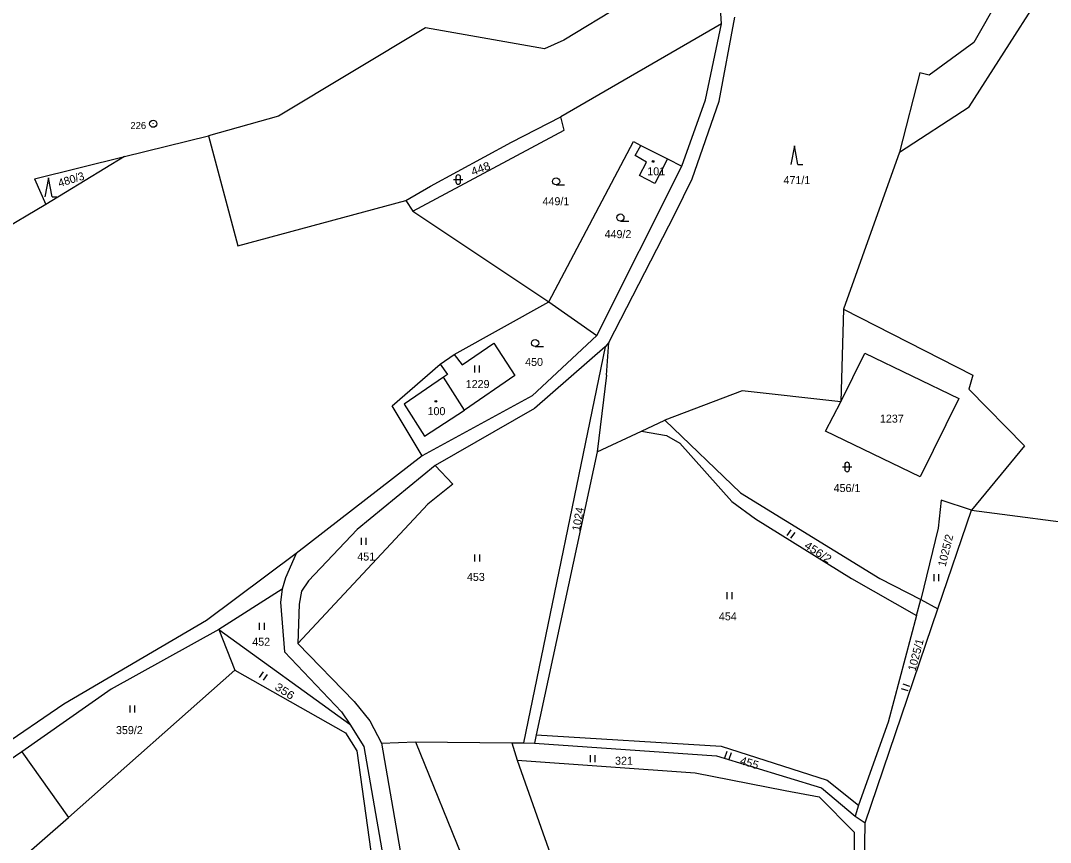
# Model space of a CAD drawing. Extents: x -744132 to -742433, y -984679 to -982287.
# Drawn here: x -743105 to -742886.3, y -983707.4 to -983532.9 of the extents above; entities that cross this region are included whole.
import ezdxf
from ezdxf.enums import TextEntityAlignment as Align

# ---------------------------------------------------------------- set-up
doc = ezdxf.new("R2010")
doc.units = 0
doc.header["$LTSCALE"] = 0.68
for name, color, linetype, lineweight in [('1', 7, 'Continuous', 25), ('3', 7, 'Continuous', 25), ('5', 7, 'Continuous', 25), ('8', 7, 'Continuous', 25)]:
    doc.layers.add(name, color=color, linetype=linetype, lineweight=lineweight)
doc.layers.add('2', color=7, linetype='Continuous')

msp = doc.modelspace()

# ---------------------------------------------------------------- linework, layer by layer
at = {"layer": '1'}
for p, q in [((-742956.14, -983533.56), (-742957.26, -983515.6)), ((-742894.51, -983523.48), (-742902.53, -983537.48)), ((-742903.5, -983551.14), (-742888.2, -983527.16)), ((-742977.21, -983529.47), (-742989.65, -983537)), ((-742956.63, -983549.96), (-742953.26, -983532.14)), ((-743018.99, -983534.41), (-743050.26, -983553.18)), ((-742993.73, -983538.86), (-743018.99, -983534.41)), ((-742956.14, -983533.56), (-742990.29, -983553.27)), ((-742959.5, -983549.65), (-742956.14, -983533.56)), ((-742989.65, -983537), (-742993.73, -983538.86)), ((-742902.53, -983537.48), (-742912, -983544.46)), ((-742914, -983543.94), (-742918.35, -983560.77)), ((-742912, -983544.46), (-742914, -983543.94)), ((-742964.56, -983563.78), (-742959.5, -983549.65)), ((-742962.39, -983566.49), (-742956.63, -983549.96)), ((-742918.35, -983560.77), (-742903.5, -983551.14)), ((-743050.26, -983553.18), (-743065.09, -983557.3)), ((-743000.72, -983558.65), (-742990.29, -983553.27)), ((-742989.58, -983556.09), (-742990.29, -983553.27)), ((-743082.91, -983561.73), (-743065.09, -983557.3)), ((-743065.09, -983557.3), (-743058.88, -983580.68)), ((-743021.72, -983573.33), (-742989.58, -983556.09)), ((-743017.91, -983568.01), (-743000.72, -983558.65)), ((-742992.82, -983592.6), (-742974.85, -983558.53)), ((-742974.85, -983558.53), (-742973.25, -983559.37)), ((-742974.44, -983561.53), (-742973.25, -983559.37)), ((-742973.25, -983559.37), (-742967.61, -983562.23)), ((-743102.08, -983566.47), (-743082.91, -983561.73)), ((-743082.91, -983561.73), (-743099.64, -983571.88)), ((-742972.06, -983562.91), (-742974.44, -983561.53)), ((-742918.35, -983560.77), (-742930.2, -983594.18)), ((-742982.6, -983599.76), (-742964.56, -983563.78)), ((-742973.54, -983565.78), (-742972.06, -983562.91)), ((-742967.61, -983562.23), (-742970.27, -983567.47)), ((-742967.61, -983562.23), (-742964.56, -983563.78)), ((-742970.27, -983567.47), (-742973.54, -983565.78)), ((-743102.08, -983566.47), (-743099.64, -983571.88)), ((-743023.21, -983571.09), (-743017.91, -983568.01)), ((-742966.04, -983573.96), (-742962.39, -983566.49)), ((-743099.64, -983571.88), (-743137.01, -983594.08)), ((-743058.88, -983580.68), (-743023.21, -983571.09)), ((-743023.21, -983571.09), (-743021.72, -983573.33)), ((-743021.72, -983573.33), (-742992.82, -983592.6)), ((-742980.03, -983601.25), (-742966.04, -983573.96)), ((-743012.88, -983603.78), (-742992.82, -983592.6)), ((-742992.82, -983592.6), (-742982.6, -983599.76)), ((-742930.2, -983594.18), (-742930.76, -983613.83)), ((-742930.2, -983594.18), (-742902.75, -983608.14)), ((-742982.6, -983599.76), (-742996.35, -983612.57)), ((-743011.23, -983605.95), (-743004.47, -983601.4)), ((-743004.47, -983601.4), (-743000.04, -983608.27)), ((-742980.83, -983602.15), (-742998.21, -983686.27)), ((-742980.83, -983602.15), (-742995.86, -983615.23)), ((-742980.03, -983601.25), (-742980.83, -983602.15)), ((-742980.53, -983608.16), (-742980.03, -983601.25)), ((-743015.87, -983605.82), (-743012.88, -983603.78)), ((-743012.88, -983603.78), (-743011.23, -983605.95)), ((-742925.68, -983603.47), (-742905.69, -983613.13)), ((-743026.07, -983614.71), (-743015.87, -983605.82)), ((-743015.87, -983605.82), (-743014.35, -983608.02)), ((-743015.18, -983608.62), (-743023.52, -983614.35)), ((-743014.35, -983608.02), (-743015.18, -983608.62)), ((-743000.04, -983608.27), (-743010.75, -983615.57)), ((-742980.53, -983608.16), (-742982.52, -983624.43)), ((-742902.75, -983608.14), (-742903.61, -983611.17)), ((-742951.74, -983611.47), (-742968.13, -983617.75)), ((-742930.76, -983613.83), (-742951.74, -983611.47)), ((-742903.61, -983611.17), (-742891.78, -983623.16)), ((-743023.52, -983614.35), (-743019.19, -983621.11)), ((-742996.35, -983612.57), (-743019.68, -983625.29)), ((-742905.69, -983613.13), (-742913.93, -983629.76)), ((-743019.68, -983625.29), (-743026.07, -983614.71)), ((-742995.86, -983615.23), (-743016.94, -983627.35)), ((-742973.15, -983620.08), (-742968.13, -983617.75)), ((-742968.13, -983617.75), (-742952.09, -983633.13)), ((-742982.52, -983624.43), (-742973.15, -983620.08)), ((-742973.15, -983620.08), (-742967.83, -983621.02)), ((-742913.93, -983629.76), (-742934.04, -983620.03)), ((-742967.83, -983621.02), (-742964.98, -983622.63)), ((-742964.98, -983622.63), (-742953.9, -983635.02)), ((-743019.68, -983625.29), (-743046.5, -983646.05)), ((-742982.52, -983624.43), (-742995.5, -983684.58)), ((-742891.78, -983623.16), (-742903.04, -983636.86)), ((-743016.94, -983627.35), (-743033.55, -983640.96)), ((-743016.94, -983627.35), (-743013.22, -983631.3)), ((-743013.22, -983631.3), (-743018.52, -983635.57)), ((-742952.09, -983633.13), (-742922.52, -983651.34)), ((-743018.52, -983635.57), (-743046.13, -983665.16)), ((-742953.9, -983635.02), (-742948.9, -983638.66)), ((-742909.46, -983634.72), (-742910.12, -983640.7)), ((-742903.04, -983636.86), (-742909.46, -983634.72)), ((-742948.9, -983638.66), (-742928.53, -983651.37)), ((-743033.55, -983640.96), (-743043.87, -983651.88)), ((-742910.12, -983640.7), (-742913.78, -983655.83)), ((-743046.5, -983646.05), (-743065.5, -983660.31)), ((-743046.5, -983646.05), (-743048.73, -983651.23)), ((-743048.73, -983651.23), (-743049.43, -983653.6)), ((-742928.53, -983651.37), (-742914.67, -983659.22)), ((-742922.52, -983651.34), (-742913.78, -983655.83)), ((-743049.43, -983653.6), (-743062.93, -983662.18)), ((-743049.43, -983653.6), (-743049.79, -983656.41)), ((-743043.87, -983651.88), (-743045.33, -983654.04)), ((-743045.33, -983654.04), (-743045.82, -983656.83)), ((-742914.67, -983659.22), (-742913.78, -983655.83)), ((-742913.78, -983655.83), (-742910.14, -983657.77)), ((-743049.79, -983656.41), (-743048.99, -983666.97)), ((-743045.82, -983656.83), (-743046.13, -983665.16)), ((-742925.58, -983703.29), (-742910.14, -983657.77)), ((-742914.67, -983659.22), (-742920.73, -983681.89)), ((-743065.5, -983660.31), (-743095.85, -983678.02)), ((-743062.93, -983662.18), (-743085.76, -983674.89)), ((-743062.93, -983662.18), (-743059.51, -983670.83)), ((-743062.93, -983662.18), (-743035.1, -983682.32)), ((-743046.13, -983665.16), (-743034.13, -983677.46)), ((-743048.99, -983666.97), (-743036.82, -983679.71)), ((-743094.86, -983702.13), (-743059.51, -983670.83)), ((-743059.51, -983670.83), (-743036.01, -983684.14)), ((-743085.76, -983674.89), (-743104.75, -983688.16)), ((-743034.13, -983677.46), (-743030.81, -983681.59)), ((-743095.85, -983678.02), (-743155, -983718.55)), ((-743036.82, -983679.71), (-743035.1, -983682.32)), ((-743030.81, -983681.59), (-743028.35, -983686.31)), ((-742920.73, -983681.89), (-742926.99, -983699.53)), ((-743036.01, -983684.14), (-743033.61, -983687.97)), ((-743035.1, -983682.32), (-743032.07, -983687.03)), ((-743028.35, -983686.31), (-743021.12, -983686.03)), ((-743028.35, -983686.31), (-743024.4, -983709.2)), ((-743021.12, -983686.03), (-743000.66, -983686.24)), ((-743021.12, -983686.03), (-743009.21, -983715.33)), ((-743000.66, -983686.24), (-742999.53, -983689.92)), ((-743000.66, -983686.24), (-742998.21, -983686.27)), ((-742998.21, -983686.27), (-742995.84, -983686.31)), ((-742995.5, -983684.58), (-742995.84, -983686.31)), ((-742995.84, -983686.31), (-742957.17, -983689.06)), ((-742995.5, -983684.58), (-742956.23, -983686.97)), ((-743104.75, -983688.16), (-743152.82, -983721.07)), ((-743104.75, -983688.16), (-743094.86, -983702.13)), ((-743033.61, -983687.97), (-743030.61, -983709.32)), ((-743032.07, -983687.03), (-743028.31, -983708.97)), ((-742956.23, -983686.97), (-742933.68, -983694.17)), ((-742999.53, -983689.92), (-742989.76, -983717.46)), ((-742999.53, -983689.92), (-742961.7, -983692.62)), ((-742957.17, -983689.06), (-742934.85, -983695.83)), ((-742961.7, -983692.62), (-742942.63, -983696.39)), ((-742933.68, -983694.17), (-742926.99, -983699.53)), ((-742942.63, -983696.39), (-742935.38, -983697.75)), ((-742934.85, -983695.83), (-742927.74, -983701.85)), ((-742935.38, -983697.75), (-742927.91, -983705.22)), ((-742926.99, -983699.53), (-742927.74, -983701.85)), ((-742927.74, -983701.85), (-742925.58, -983703.29)), ((-743144.38, -983745.38), (-743094.86, -983702.13)), ((-742925.79, -983717.32), (-742925.58, -983703.29)), ((-742927.91, -983705.22), (-742927.99, -983716.66))]:
    msp.add_line(p, q, dxfattribs=at)
for points in [[(-742934.04, -983620.03), (-742930.76, -983613.83), (-742925.68, -983603.47)], [(-743019.19, -983621.11), (-743010.75, -983615.57), (-743015.18, -983608.62)], [(-742910.14, -983657.77), (-742903.04, -983636.86), (-742875.93, -983640.4)]]:
    msp.add_lwpolyline(points, dxfattribs=at)
at = {"layer": '3'}
for p, q in [((-742939.88, -983563.45), (-742938.884, -983563.45)), ((-743012.551, -983566.121), (-743012.551, -983567.122)), ((-743011.549, -983567.122), (-743011.549, -983566.121)), ((-743013.051, -983566.621), (-743011.049, -983566.621)), ((-742991.253, -983567.76), (-742989.503, -983567.76)), ((-743098.34, -983570.28), (-743097.344, -983570.28)), ((-742977.593, -983575.43), (-742975.843, -983575.43)), ((-742995.713, -983602.1), (-742993.963, -983602.1)), ((-743008.511, -983607.61), (-743008.511, -983606.11)), ((-743007.51, -983607.61), (-743007.51, -983606.11)), ((-742929.951, -983627.171), (-742929.951, -983628.172)), ((-742928.949, -983628.172), (-742928.949, -983627.171)), ((-742930.451, -983627.671), (-742928.449, -983627.671)), ((-743032.581, -983644.22), (-743032.581, -983642.72)), ((-743031.58, -983644.22), (-743031.58, -983642.72)), ((-742942.188, -983642.237), (-742941.328, -983641.008)), ((-742941.368, -983642.811), (-742940.508, -983641.582)), ((-743008.491, -983647.78), (-743008.491, -983646.28)), ((-743007.49, -983647.78), (-743007.49, -983646.28)), ((-742910.941, -983651.93), (-742910.941, -983650.43)), ((-742909.94, -983651.93), (-742909.94, -983650.43)), ((-742954.891, -983655.76), (-742954.891, -983654.26)), ((-742953.89, -983655.76), (-742953.89, -983654.26)), ((-743054.231, -983662.29), (-743054.231, -983660.79)), ((-743053.23, -983662.29), (-743053.23, -983660.79)), ((-743054.254, -983672.424), (-743053.415, -983671.181)), ((-743053.424, -983672.984), (-743052.585, -983671.741)), ((-742916.466, -983675.253), (-742917.885, -983674.765)), ((-742916.14, -983674.306), (-742917.559, -983673.818)), ((-743081.721, -983679.83), (-743081.721, -983678.33)), ((-743080.72, -983679.83), (-743080.72, -983678.33)), ((-742955.433, -983689.424), (-742954.945, -983688.005)), ((-742954.486, -983689.75), (-742953.998, -983688.331)), ((-742983.961, -983690.39), (-742983.961, -983688.89)), ((-742982.96, -983690.39), (-742982.96, -983688.89))]:
    msp.add_line(p, q, dxfattribs=at)
for points in [[(-742939.88, -983563.45), (-742940.63, -983559.45), (-742941.38, -983563.45)], [(-743098.34, -983570.28), (-743099.09, -983566.28), (-743099.84, -983570.28)]]:
    msp.add_lwpolyline(points, dxfattribs=at)
for centre in [(-742991.2529, -983567.0098), (-742977.5929, -983574.6798), (-742995.7129, -983601.3498)]:
    msp.add_circle(centre, 0.75, dxfattribs=at)
for centre, start, end in [((-743012.05, -983566.1209), 0, 180), ((-743012.05, -983567.1209), 180, 359.98789), ((-742929.45, -983627.1709), 0, 180), ((-742929.45, -983628.1709), 180, 359.98789)]:
    msp.add_arc(centre, 0.5, start, end, dxfattribs=at)
at = {"layer": '5'}
for centre in [(-742970.6468, -983562.7692), (-743016.7968, -983613.7292)]:
    msp.add_circle(centre, 0.175, dxfattribs=at)
at = {"layer": '8'}
for radius in [0.75, 0.03]:
    msp.add_circle((-743076.85, -983554.7698), radius, dxfattribs=at)

# ---------------------------------------------------------------- texts
at = {"layer": '2'}
for s, rotation, width, p in [('448', 21, 1.1, (-743008.947, -983565.836)), ('456/2', 327, 1.1, (-742938.701, -983644.766)), ('356', 327, 1.15, (-743051.191, -983674.816)), ('455', 343, 1.05, (-742952.334, -983690.736))]:
    msp.add_text(s, height=1.7, rotation=rotation, dxfattribs=dict(at, width=width)).set_placement(p)
for s, p in [('101', (-742971.89, -983565.715)), ('471/1', (-742942.96, -983567.585)), ('449/1', (-742994.14, -983572.065)), ('449/2', (-742980.96, -983579.055)), ('450', (-742997.84, -983606.215)), ('1229', (-743010.46, -983610.905)), ('100', (-743018.57, -983616.665)), ('456/1', (-742932.31, -983632.995)), ('451', (-743033.49, -983647.545)), ('453', (-743010.2, -983651.875)), ('454', (-742956.68, -983660.245)), ('452', (-743055.81, -983665.645)), ('359/2', (-743084.75, -983684.415)), ('321', (-742978.74, -983690.925))]:
    msp.add_text(s, height=1.7, dxfattribs=at).set_placement(p)
for s, rotation, p in [('480/3', 17, (-743096.755, -983568.236)), ('1024', 80, (-742986.221, -983641.383)), ('1025/2', 76, (-742908.547, -983648.972)), ('1025/1', 75, (-742914.939, -983671.159))]:
    msp.add_text(s, height=1.7, rotation=rotation, dxfattribs=at).set_placement(p)
msp.add_text('1237', height=1.7, dxfattribs=at).set_placement((-742919.94, -983618.255), align=Align.CENTER)
at = {"layer": '8'}
msp.add_text('226', height=1.5, dxfattribs=at).set_placement((-743078.349, -983555.887), align=Align.RIGHT)

doc.saveas('drawing.dxf')
